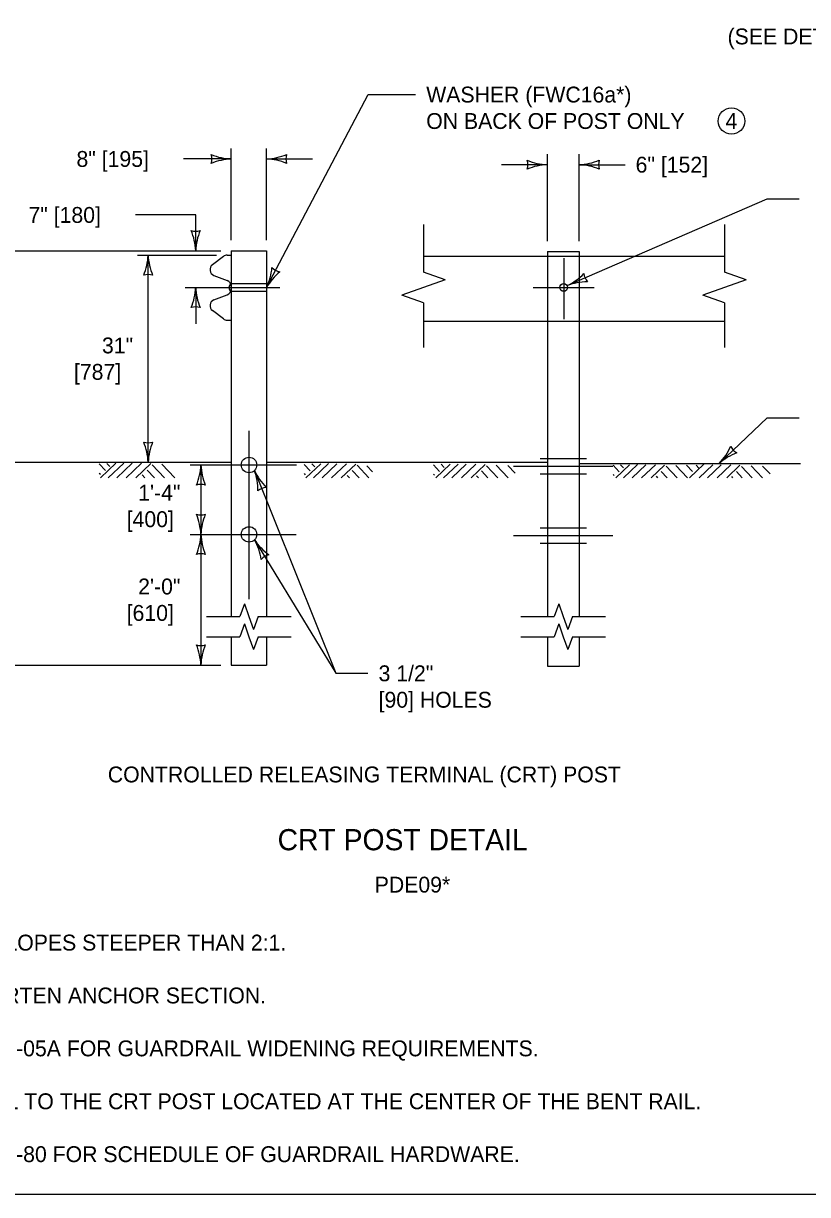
# Model space of a CAD drawing. Extents: x 49991.4 to 50021, y 49987.6 to 50011.4.
# Drawn here: x 50007.887 to 50010.85, y 49987.799 to 49992.227 of the extents above; entities that cross this region are included whole.
import ezdxf

# ---------------------------------------------------------------- set-up
doc = ezdxf.new("R2010")
doc.units = 0
for name, color, linetype in [('Level 1', 7, 'Continuous'), ('Level 2', 7, 'Continuous'), ('Level 3', 7, 'Continuous'), ('Level 4', 7, 'Continuous'), ('Level 5', 7, 'Continuous'), ('Level 6', 7, 'Continuous')]:
    doc.layers.add(name, color=color, linetype=linetype)

msp = doc.modelspace()

# ---------------------------------------------------------------- linework, layer by layer
at = {"layer": 'Level 1'}
for p, q in [((50008.6425, 49991.3463), (50008.6009, 49991.3146)), ((50008.6569, 49991.3511), (50008.6722, 49991.3511)), ((50008.6722, 49991.3678), (50008.8055, 49991.3678)), ((50008.6722, 49991.3678), (50008.6722, 49989.9842)), ((50008.8055, 49991.3678), (50008.8055, 49989.9842)), ((50009.3987, 49991.3475), (50010.5361, 49991.3475)), ((50009.8669, 49991.3642), (50009.9869, 49991.3642)), ((50009.8669, 49991.3642), (50009.8669, 49991.3475)), ((50009.9869, 49991.3642), (50009.9869, 49991.3475)), ((50008.6065, 49991.2743), (50008.6569, 49991.2545)), ((50008.6065, 49991.1816), (50008.6569, 49991.2014)), ((50008.6425, 49991.1096), (50008.6009, 49991.1413)), ((50008.6569, 49991.1048), (50008.6722, 49991.1048)), ((50009.3987, 49991.1011), (50010.5361, 49991.1011)), ((50009.8669, 49991.1011), (50009.8669, 49989.9842)), ((50009.9869, 49991.1011), (50009.9869, 49989.9842)), ((50007.8408, 49990.5679), (50008.6722, 49990.5679)), ((50008.1733, 49990.5613), (50008.1963, 49990.5368)), ((50008.1784, 49990.5094), (50008.2359, 49990.5638)), ((50008.2021, 49990.5635), (50008.2129, 49990.552)), ((50008.2074, 49990.5094), (50008.2657, 49990.5642)), ((50008.2393, 49990.5094), (50008.2971, 49990.5638)), ((50008.2756, 49990.5094), (50008.3333, 49990.5638)), ((50008.3116, 49990.5094), (50008.3679, 49990.5626)), ((50008.3547, 49990.5384), (50008.3822, 49990.5094)), ((50008.3737, 49990.5583), (50008.4203, 49990.5094)), ((50008.4101, 49990.5607), (50008.4583, 49990.5094)), ((50008.8055, 49990.5679), (50009.8669, 49990.5679)), ((50008.9473, 49990.5598), (50008.9709, 49990.5353)), ((50008.9543, 49990.5094), (50009.0105, 49990.562)), ((50008.9761, 49990.5617), (50008.9874, 49990.5502)), ((50008.9835, 49990.5094), (50009.04, 49990.5626)), ((50009.0155, 49990.5094), (50009.0717, 49990.562)), ((50009.0515, 49990.5094), (50009.1077, 49990.562)), ((50009.0881, 49990.5094), (50009.1425, 49990.5607)), ((50009.1293, 49990.5367), (50009.1551, 49990.5094)), ((50009.1482, 49990.5564), (50009.1927, 49990.5094)), ((50009.1842, 49990.5547), (50009.2063, 49990.5313)), ((50009.4367, 49990.5578), (50009.4597, 49990.5334)), ((50009.4454, 49990.5094), (50009.4993, 49990.5605)), ((50009.4655, 49990.56), (50009.4763, 49990.5485)), ((50009.4745, 49990.5094), (50009.5291, 49990.5607)), ((50009.5063, 49990.5094), (50009.5605, 49990.5605)), ((50009.5427, 49990.5094), (50009.5965, 49990.5605)), ((50009.5786, 49990.5094), (50009.6313, 49990.5592)), ((50009.6181, 49990.535), (50009.6424, 49990.5094)), ((50009.6371, 49990.5548), (50009.68, 49990.5094)), ((50009.6731, 49990.5574), (50009.7186, 49990.5094)), ((50009.717, 49990.5552), (50009.7449, 49990.5262)), ((50009.9869, 49990.5634), (50010.8234, 49990.5634)), ((50010.1149, 49990.5563), (50010.1382, 49990.5318)), ((50010.1256, 49990.5094), (50010.1778, 49990.5586)), ((50010.1437, 49990.5583), (50010.1545, 49990.5468)), ((50010.1546, 49990.5094), (50010.2073, 49990.5592)), ((50010.1867, 49990.5094), (50010.2388, 49990.5586)), ((50010.2227, 49990.5094), (50010.275, 49990.5586)), ((50010.2591, 49990.5094), (50010.3101, 49990.5574)), ((50010.3153, 49990.553), (50010.3569, 49990.5094)), ((50010.3518, 49990.5557), (50010.3958, 49990.5094)), ((50010.3921, 49990.5569), (50010.4152, 49990.5324)), ((50010.4044, 49990.5094), (50010.4579, 49990.56)), ((50010.4289, 49990.5574), (50010.4397, 49990.5458)), ((50010.4408, 49990.5094), (50010.4925, 49990.5581)), ((50010.4726, 49990.5094), (50010.5239, 49990.5577)), ((50010.5089, 49990.5094), (50010.5599, 49990.5577)), ((50010.5448, 49990.5094), (50010.5947, 49990.5564)), ((50010.6005, 49990.5521), (50010.6408, 49990.5094)), ((50010.6365, 49990.5547), (50010.6793, 49990.5094)), ((50010.6804, 49990.5526), (50010.7082, 49990.5235)), ((50008.1733, 49990.5268), (50008.1776, 49990.5223)), ((50008.336, 49990.5199), (50008.3458, 49990.5094)), ((50008.9473, 49990.525), (50008.9517, 49990.5206)), ((50009.1101, 49990.5181), (50009.1185, 49990.5094)), ((50009.4367, 49990.5233), (50009.4405, 49990.5188)), ((50009.5994, 49990.5166), (50009.6062, 49990.5094)), ((50010.1149, 49990.5216), (50010.1193, 49990.5173)), ((50010.2777, 49990.5146), (50010.2826, 49990.5094)), ((50010.2966, 49990.5332), (50010.3192, 49990.5094)), ((50010.5628, 49990.5138), (50010.567, 49990.5094)), ((50010.5815, 49990.5324), (50010.6033, 49990.5094)), ((50008.6722, 49989.908), (50008.6722, 49989.8012)), ((50008.8055, 49989.908), (50008.8055, 49989.8012)), ((50009.8669, 49989.908), (50009.8669, 49989.7967)), ((50009.9869, 49989.908), (50009.9869, 49989.7967)), ((50008.6722, 49989.8012), (50008.8055, 49989.8012)), ((50009.8669, 49989.7967), (50009.9869, 49989.7967))]:
    msp.add_line(p, q, dxfattribs=at)
msp.add_lwpolyline([(49999.3835, 49998.9992), (50016.7501, 49998.9992), (50016.7501, 49987.7988), (49999.3835, 49987.7988)], close=True, dxfattribs=at)
for centre, radius in [((50009.9287, 49991.2288), 0.0147), ((50008.7394, 49990.5575), 0.0292), ((50008.7394, 49990.295), 0.0292)]:
    msp.add_circle(centre, radius, dxfattribs=at)
for centre, radius, start, end in [((50008.6568, 49991.3274), 0.0237, 89.8747, 127.1838), ((50008.6151, 49991.296), 0.0233, 127.3362, 248.5347), ((50008.6489, 49991.2326), 0.0233, 359.8738, 70.01), ((50008.6489, 49991.2233), 0.0233, 289.99, 0.1262), ((50008.6801, 49991.228), 0.0167, 118.2768, 241.7232), ((50008.6151, 49991.1599), 0.0233, 111.4653, 232.6638), ((50008.6568, 49991.1285), 0.0237, 232.8162, 270.1253)]:
    msp.add_arc(centre, radius, start, end, dxfattribs=at)
at = {"layer": 'Level 2'}
msp.add_circle((50010.5627, 49991.8581), 0.05, dxfattribs=at)
at = {"layer": 'Level 3'}
for p, q in [((50008.8055, 49991.2288), (50009.1893, 49991.958)), ((50009.1893, 49991.958), (50009.3689, 49991.958)), ((50008.6722, 49991.4078), (50008.6722, 49991.7546)), ((50008.8055, 49991.4078), (50008.8055, 49991.7546)), ((50009.8669, 49991.4042), (50009.8669, 49991.733)), ((50009.9869, 49991.4042), (50009.9869, 49991.733)), ((50008.6722, 49991.7146), (50008.4922, 49991.7146)), ((50008.8055, 49991.7146), (50008.979, 49991.7146)), ((50009.8669, 49991.693), (50009.6934, 49991.693)), ((50009.9869, 49991.693), (50010.1603, 49991.693)), ((50009.9417, 49991.2356), (50010.6977, 49991.5639)), ((50010.6977, 49991.5639), (50010.8189, 49991.5639)), ((50008.5377, 49991.5029), (50008.3107, 49991.5029)), ((50008.5377, 49991.3678), (50008.5377, 49991.5029)), ((50007.6036, 49991.3678), (50008.6322, 49991.3678)), ((50008.3181, 49991.3511), (50008.6169, 49991.3511)), ((50008.3581, 49990.5679), (50008.3581, 49991.3511)), ((50008.5377, 49991.2288), (50008.5377, 49991.0917)), ((50010.5163, 49990.5634), (50010.6977, 49990.7362)), ((50010.6977, 49990.7362), (50010.8189, 49990.7362)), ((50008.5574, 49990.5575), (50008.5574, 49990.295)), ((50008.76, 49990.5368), (50009.0677, 49989.7698)), ((50008.5574, 49990.295), (50008.5574, 49989.8012)), ((50008.76, 49990.2743), (50009.0677, 49989.7698)), ((50007.6036, 49989.8012), (50008.6322, 49989.8012)), ((50009.0677, 49989.7698), (50009.1889, 49989.7698))]:
    msp.add_line(p, q, dxfattribs=at)
for centre, radius, start, end in [((50008.6814, 49991.9367), 0.2223, 247.456, 267.6395), ((50008.544, 49991.7146), 0.0548, 342.1388, 17.8612), ((50008.794, 49991.9473), 0.233, 272.8273, 292.0772), ((50008.9337, 49991.7146), 0.0548, 162.1388, 197.8612), ((50008.6837, 49991.4819), 0.233, 92.8273, 112.0772), ((50008.7964, 49991.4925), 0.2223, 67.456, 87.6395), ((50009.876, 49991.9151), 0.2223, 247.456, 267.6395), ((50009.7387, 49991.693), 0.0548, 342.1388, 17.8612), ((50009.8784, 49991.4603), 0.233, 92.8273, 112.0772), ((50009.9754, 49991.9257), 0.233, 272.8273, 292.0772), ((50009.9777, 49991.4709), 0.2223, 67.456, 87.6395), ((50010.1151, 49991.693), 0.0548, 162.1388, 197.8612), ((50008.5377, 49991.496), 0.0548, 252.1388, 287.8612), ((50008.305, 49991.3563), 0.233, 2.8273, 22.0772), ((50008.7598, 49991.3586), 0.2223, 157.456, 177.6395), ((50008.136, 49991.3603), 0.2223, 337.456, 357.6395), ((50008.5908, 49991.3626), 0.233, 182.8273, 202.0772), ((50008.5942, 49991.327), 0.233, 335.067, 354.3168), ((50008.9978, 49991.1172), 0.2223, 129.6957, 149.8792), ((50008.8652, 49991.3422), 0.0548, 224.3785, 260.1008), ((50008.3581, 49991.2229), 0.0548, 72.1388, 107.8612), ((50009.8385, 49991.4445), 0.233, 296.3011, 315.5509), ((50010.0218, 49991.0282), 0.2223, 90.9298, 111.1133), ((50010.0593, 49991.2867), 0.0548, 185.6126, 221.335), ((50008.3155, 49991.2379), 0.2223, 337.456, 357.6395), ((50008.7704, 49991.2403), 0.233, 182.8273, 202.0772), ((50008.5377, 49991.1006), 0.0548, 72.1388, 107.8612), ((50008.3581, 49990.6961), 0.0548, 252.1388, 287.8612), ((50008.1254, 49990.5564), 0.233, 2.8273, 22.0772), ((50008.5803, 49990.5588), 0.2223, 157.456, 177.6395), ((50010.3475, 49990.724), 0.233, 316.4407, 335.6905), ((50010.6092, 49990.6518), 0.0548, 205.7522, 241.4745), ((50010.6629, 49990.3962), 0.2223, 111.0694, 131.2529), ((50008.3352, 49990.5666), 0.2223, 337.456, 357.6395), ((50008.7901, 49990.569), 0.233, 182.8273, 202.0772), ((50008.5504, 49990.4626), 0.2223, 359.3154, 19.4989), ((50008.9717, 49990.6342), 0.233, 204.6867, 223.9365), ((50008.5574, 49990.4293), 0.0548, 72.1388, 107.8612), ((50008.8078, 49990.4178), 0.0548, 93.9982, 129.7206), ((50008.5574, 49990.4232), 0.0548, 252.1388, 287.8612), ((50008.3246, 49990.2835), 0.233, 2.8273, 22.0772), ((50008.7795, 49990.2858), 0.2223, 157.456, 177.6395), ((50008.3352, 49990.3041), 0.2223, 337.456, 357.6395), ((50008.7901, 49990.3065), 0.233, 182.8273, 202.0772), ((50008.5656, 49990.1665), 0.2223, 8.8352, 29.0187), ((50008.9527, 49990.4053), 0.233, 214.2065, 233.4563), ((50008.5574, 49990.1668), 0.0548, 72.1388, 107.8612), ((50008.8268, 49990.1649), 0.0548, 103.518, 139.2403), ((50008.5574, 49989.9294), 0.0548, 252.1388, 287.8612), ((50008.3246, 49989.7897), 0.233, 2.8273, 22.0772), ((50008.7795, 49989.7921), 0.2223, 157.456, 177.6395)]:
    msp.add_arc(centre, radius, start, end, dxfattribs=at)
at = {"layer": 'Level 4'}
for p, q in [((50009.8669, 49991.3475), (50009.8669, 49991.1011)), ((50009.9869, 49991.3475), (50009.9869, 49991.1011)), ((50008.8056, 49991.2427), (50008.6722, 49991.2427)), ((50008.8056, 49991.2133), (50008.6722, 49991.2133)), ((50009.8392, 49990.5821), (50010.0146, 49990.5821)), ((50009.8392, 49990.5238), (50010.0146, 49990.5238)), ((50009.8392, 49990.3196), (50010.0146, 49990.3196)), ((50009.8392, 49990.2613), (50010.0146, 49990.2613))]:
    msp.add_line(p, q, dxfattribs=at)
at = {"layer": 'Level 5'}
for p, q in [((50009.9287, 49991.3392), (50009.9287, 49991.1093)), ((50008.4977, 49991.2288), (50008.8558, 49991.2288)), ((50009.8137, 49991.2288), (50010.0436, 49991.2288)), ((50008.7389, 49990.6869), (50008.7389, 49990.0497)), ((50008.5174, 49990.5575), (50008.9189, 49990.5575)), ((50009.7389, 49990.553), (50010.1148, 49990.553)), ((50008.5174, 49990.295), (50008.9179, 49990.295)), ((50009.7389, 49990.2904), (50010.1148, 49990.2904))]:
    msp.add_line(p, q, dxfattribs=at)
at = {"layer": 'Level 6'}
for p, q in [((50009.3987, 49991.4662), (50009.3987, 49991.2871)), ((50010.5361, 49991.4662), (50010.5361, 49991.2871)), ((50009.4809, 49991.2579), (50009.3987, 49991.2871)), ((50009.4809, 49991.2579), (50009.3987, 49991.2288)), ((50010.6183, 49991.2579), (50010.5361, 49991.2871)), ((50010.6183, 49991.2579), (50010.5361, 49991.2288)), ((50009.3987, 49991.2288), (50009.3165, 49991.1996)), ((50009.3987, 49991.1705), (50009.3165, 49991.1996)), ((50010.5361, 49991.2288), (50010.4539, 49991.1996)), ((50010.5361, 49991.1705), (50010.4539, 49991.1996)), ((50009.3987, 49991.1705), (50009.3987, 49991.0011)), ((50010.5361, 49991.1705), (50010.5361, 49991.0011)), ((50008.7216, 49990.033), (50008.7043, 49989.9842)), ((50008.7216, 49990.033), (50008.7389, 49989.9842)), ((50009.9096, 49990.033), (50009.8923, 49989.9842)), ((50009.9096, 49990.033), (50009.9269, 49989.9842)), ((50008.5789, 49989.9842), (50008.7043, 49989.9842)), ((50008.7389, 49989.9842), (50008.7561, 49989.9354)), ((50008.7734, 49989.9842), (50008.7561, 49989.9354)), ((50008.7734, 49989.9842), (50008.8989, 49989.9842)), ((50009.7669, 49989.9842), (50009.8923, 49989.9842)), ((50009.9269, 49989.9842), (50009.9442, 49989.9354)), ((50009.9614, 49989.9842), (50009.9442, 49989.9354)), ((50009.9614, 49989.9842), (50010.0869, 49989.9842)), ((50008.7216, 49989.9568), (50008.7043, 49989.908)), ((50008.7216, 49989.9568), (50008.7389, 49989.908)), ((50009.9096, 49989.9568), (50009.8923, 49989.908)), ((50009.9096, 49989.9568), (50009.9269, 49989.908)), ((50008.5789, 49989.908), (50008.7043, 49989.908)), ((50008.7389, 49989.908), (50008.7561, 49989.8592)), ((50008.7734, 49989.908), (50008.7561, 49989.8592)), ((50008.7734, 49989.908), (50008.8989, 49989.908)), ((50009.7669, 49989.908), (50009.8923, 49989.908)), ((50009.9269, 49989.908), (50009.9442, 49989.8592)), ((50009.9614, 49989.908), (50009.9442, 49989.8592)), ((50009.9614, 49989.908), (50010.0869, 49989.908))]:
    msp.add_line(p, q, dxfattribs=at)

# ---------------------------------------------------------------- texts
at = {"layer": 'Level 2'}
for s, height, p in [('(SEE DETAIL)', 0.06, (50010.5479, 49992.1478)), ('WASHER (FWC16a*)', 0.06, (50009.409, 49991.9281)), ('ON BACK OF POST ONLY', 0.06, (50009.409, 49991.8281)), ('4', 0.06, (50010.5399, 49991.8281)), ('8" [195]', 0.06, (50008.0872, 49991.6846)), ('6" [152]', 0.06, (50010.2003, 49991.663)), ('7" [180]', 0.06, (50007.9057, 49991.4729)), ('31"', 0.06, (50008.1836, 49990.9795)), ('[787]', 0.06, (50008.0777, 49990.8795)), ('1\'-4" ', 0.06, (50008.3204, 49990.4225)), ('[400]', 0.06, (50008.2769, 49990.3225)), ('2\'-0"', 0.06, (50008.3204, 49990.0681)), ('[610]', 0.06, (50008.2769, 49989.9681)), ('3 1/2" ', 0.06, (50009.2289, 49989.7398)), ('[90] HOLES', 0.06, (50009.2289, 49989.6398)), ('CONTROLLED RELEASING TERMINAL (CRT) POST', 0.06, (50008.2056, 49989.3573)), ('CRT POST DETAIL', 0.08, (50008.8473, 49989.1007)), ('PDE09*', 0.06, (50009.2143, 49988.9407)), ('DO NOT INSTALL ON SLOPES STEEPER THAN 2:1.', 0.06, (50006.9405, 49988.7216)), ('DO NOT OMIT OR SHORTEN ANCHOR SECTION.', 0.06, (50006.9405, 49988.5216)), ('SEE DTL. DWG. NO. 606-05A FOR GUARDRAIL WIDENING REQUIREMENTS.', 0.06, (50006.9405, 49988.3216)), ('DO NOT BOLT THE RAIL TO THE CRT POST LOCATED AT THE CENTER OF THE BENT RAIL.', 0.06, (50006.9405, 49988.1216)), ('SEE DTL. DWG. NO. 606-80 FOR SCHEDULE OF GUARDRAIL HARDWARE.', 0.06, (50006.9405, 49987.9216))]:
    msp.add_text(s, height=height, dxfattribs=at).set_placement(p)

doc.saveas('drawing.dxf')
